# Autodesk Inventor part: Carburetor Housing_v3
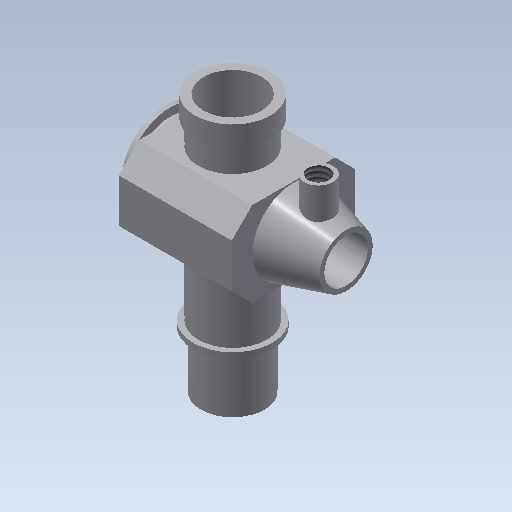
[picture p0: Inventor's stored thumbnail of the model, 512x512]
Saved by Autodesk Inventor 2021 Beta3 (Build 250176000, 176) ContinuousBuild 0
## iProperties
Created: 2012-08
Part Number: Carburetor Housing_v3
Material: Aluminum 6061
Document SubType Name: Modeling
Designer: John
Density: 2.71 g/cm^3
Mass: 9.58727 g
Surface Area: 43.1099 cm^2
Volume: 3.53774 cm^3
Appearance: Aluminum - Flat
Author: John
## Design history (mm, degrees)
sketch "Sketch1"
  geometry: L1 (-9.614, -8.788)-(9.614, -8.788); L2 (9.614, -8.788)-(9.614, 8.788); L3 (9.614, 8.788)-(-9.614, 8.788); L4 (-9.614, 8.788)-(-9.614, -8.788); L5 (-9.614, -8.788)-(9.614, 8.788); 2 further points
  constraints: 10 end point, 2 parallel, 1 coincident, 1 horizontal, 1 midpoint, 1 perpendicular
  dimensions: "d0" = 19.2278 distance of L2.end L3.end; "d2" = 17.5768 distance of L1.end L2.end
extrude "Extrusion1" new body sketch "Sketch1" stored distance "d3" = 13.1572; taper "d4" = 0 deg
sketch "Sketch2"
  geometry: L1 (9.614, 8.788)-(-9.614, 8.788) reference; L2 (-9.614, -8.788)-(9.614, -8.788) reference; L3 (0, 8.788)-(0, -8.788); C1 r 5.321 at (0, 0.686)
  constraints: 2 end point, 2 midpoint, 1 centre point, 1 point on line
  dimensions: "d5" = 10.6426 diameter of C1; "d9" = 8.1026 distance from line of L1 C1.centre
extrude "Extrusion2" join sketch "Sketch2" distance "d7" = 7.0612; taper "d8" = 0 deg
sketch "Sketch8"
  geometry: C1 r 5.321 at (0, 0) reference; C2 r 5.867 at (0, 0); 1 further point
  constraints: 1 centre point, 1 coincident
  dimensions: "d30" = 11.7348 diameter of C2
extrude "Extrusion6" join sketch "Sketch8" distance "d114" = 8.763; taper "d115" = 0 deg
sketch "Sketch3"
  geometry: C1 r 5.321 at (0, 0.686) reference; C2 r 5.321 at (0, 0.686)
  constraints: 1 centre point, 1 coincident
  dimensions: "d10" = 10.6426 diameter of C2
extrude "Extrusion3" join sketch "Sketch3" distance "d32" = 3.2512; taper "d33" = 0 deg
sketch "Sketch4"
  geometry: L1 (0, 0)-(19.228, -13.157); C1 r 5.715 at (9.614, -6.579)
  constraints: 2 end point, 1 centre point, 1 midpoint
  dimensions: "d13" = 11.43 diameter of C1
extrude "Extrusion4" join sketch "Sketch4" distance "d11" = 10.2616; taper "d12" = 0 deg
sketch "Sketch5"
  geometry: C1 r 5.715 at (0, 0) reference; C2 r 6.96 at (0, 0); 1 further point
  constraints: 1 centre point, 1 coincident
  dimensions: "d17" = 13.9192 diameter of C2
extrude "Extrusion5" join sketch "Sketch5" distance "d111" = 0.8382; taper "d112" = 0 deg
sketch "Sketch15"
  geometry: L1 (-16.967, 0)-(-16.967, 4.14); L2 (6.007, -6.579)-(6.007, -16.84) reference; L3 (-4.635, -16.84)-(-4.635, -6.579) reference; L4 (-4.635, -6.579)-(-8.788, -6.579) reference; L5 (-8.788, -6.579)-(-8.788, 6.579) reference; L6 (-8.788, 6.579)-(-4.635, 6.579) reference; L7 (-4.635, 6.579)-(-4.635, 10.389) reference; L8 (-4.635, 10.389)-(-5.182, 10.389) reference; L9 (-5.182, 10.389)-(-5.182, 13.64) reference; L10 (-5.182, 13.64)-(6.553, 13.64) reference; L11 (6.553, 13.64)-(6.553, 10.389) reference; L12 (6.553, 10.389)-(6.007, 10.389) reference; L13 (6.007, 10.389)-(6.007, 6.579) reference; L14 (6.007, 6.579)-(8.788, 6.579) reference; L15 (8.788, 6.579)-(8.788, 5.715) reference; L16 (8.788, 5.715)-(10.389, 5.715) reference; L17 (10.389, 5.715)-(10.389, 6.96) reference; L18 (10.389, 6.96)-(11.074, 6.96) reference; L19 (11.074, 6.96)-(11.074, -6.96) reference; L20 (11.074, -6.96)-(10.389, -6.96) reference; L21 (10.389, -6.96)-(10.389, -5.715) reference; L22 (10.389, -5.715)-(8.788, -5.715) reference; L23 (8.788, -5.715)-(8.788, -6.579) reference; L24 (8.788, -6.579)-(6.007, -6.579) reference; L25 (-8.788, 0)-(-16.967, 0); L26 (-16.967, 4.14)-(-8.788, 6.401); L27 (-8.788, 0)-(-8.788, 6.401); L28 (6.007, -16.84)-(6.845, -16.84) reference; L29 (6.845, -16.84)-(6.845, -17.678) reference; L30 (6.845, -17.678)-(5.639, -17.678) reference; L31 (5.639, -17.678)-(5.639, -26.441) reference; L32 (5.639, -26.441)-(-4.267, -26.441) reference; L33 (-4.267, -26.441)-(-4.267, -17.678) reference; L34 (-4.267, -17.678)-(-5.474, -17.678) reference; L35 (-5.474, -17.678)-(-5.474, -16.84) reference; L36 (-5.474, -16.84)-(-4.635, -16.84) reference; 1 further point
  constraints: 8 end point, 1 collinear, 1 midpoint, 1 parallel, 1 point on line
  dimensions: "d119" = 4.1402 distance of L1.start L1.end; "d136" = 8.1788 distance of L25.start L1.start; "d137" = 6.4008 distance from line of L25 L26.end
revolve "Revolution1" sketch "Sketch15" stored, may be unused: angle "d120" = 90 deg
hole "Hole2" diameter "d68" = 9.0678; stored, may be unused: countersink angle "d72" = 82 deg, drill point angle "d74" = 0 deg; dims "d69" = 19.05, "d70" = 9.525, "d71" = 6.35, "d73" = 16.8402, "d105" = 25.4, "d106" = 25.4
hole "Hole4" diameter "d153" = 3.302; stored, may be unused: countersink angle "d157" = 82 deg, drill point angle "d159" = 118 deg; dims "d151" = 25.4, "d152" = 25.4, "d154" = 19.05, "d155" = 9.525, "d156" = 6.35, "d158" = 25.4
chamfer "Chamfer1" distance "d101" = 3.175; stored, may be unused: second distance "d102" = 3.175, angle "d103" = 45 deg
body "Solid1"
extrude "Extrusion7" join sketch "Sketch4" distance "d15" = 2.286; taper "d16" = 0 deg
extrude "Extrusion8" join sketch "Sketch5" distance "d19" = 0.6858; taper "d20" = 0 deg
sketch "Sketch17"
  geometry: L1 (-9.614, -8.788)-(-9.614, 8.788) reference; L2 (-9.614, 8.788)-(-5.715, 8.788) reference; L3 (-5.715, 8.788)-(-5.715, 10.389) reference; L4 (-5.715, 10.389)-(-6.96, 10.389) reference; L5 (-6.96, 10.389)-(-6.96, 11.074) reference; L6 (-6.96, 11.074)-(6.96, 11.074) reference; L7 (6.96, 11.074)-(6.96, 10.389) reference; L8 (6.96, 10.389)-(5.715, 10.389) reference; L9 (5.715, 10.389)-(5.715, 8.788) reference; L10 (5.715, 8.788)-(9.614, 8.788) reference; L11 (9.614, 8.788)-(9.614, -8.788) reference; L12 (9.614, -8.788)-(6.401, -8.788) reference; L13 (6.401, -8.788)-(4.14, -16.967) reference; L14 (4.14, -16.967)-(-4.14, -16.967) reference; L15 (-4.14, -16.967)-(-6.401, -8.788) reference; L16 (-6.401, -8.788)-(-9.614, -8.788) reference; L17 (0, -16.967)-(0, -12.7); C1 r 2.223 at (0, -12.7); 1 further point
  constraints: 2 end point, 1 centre point, 1 coincident, 1 midpoint, 1 perpendicular
  dimensions: "d138" = 4.2672 distance of L17.start L17.end; "d139" = 4.445 diameter of C1
extrude "Extrusion9" join sketch "Sketch17" distance "d140" = 9.525; taper "d141" = 0 deg
hole "Hole1" diameter "d45" = 10.5918; stored, may be unused: countersink angle "d49" = 82 deg, drill point angle "d51" = 0 deg; dims "d43" = 25.4, "d44" = 25.4, "d46" = 19.05, "d47" = 9.525, "d48" = 6.35, "d50" = 16.8402
hole "Hole3" diameter "d144" = 6.8072; stored, may be unused: countersink angle "d148" = 82 deg, drill point angle "d150" = 118 deg; dims "d145" = 19.05, "d146" = 9.525, "d147" = 6.35, "d149" = 25.4, "d160" = 25.4, "d161" = 25.4
sketch "Sketch12"
  geometry: C1 r 5.321 at (0, 0) reference; C2 r 6.159 at (0, 0); 1 further point
  constraints: 1 centre point, 1 coincident
  dimensions: "d109" = 12.319 diameter of C2
sketch "Sketch13"
  geometry: C1 r 6.159 at (0, 0) reference; C2 r 4.953 at (0, 0)
  constraints: 1 centre point, 1 coincident
  dimensions: "d113" = 9.906 diameter of C2
node "Project Cut Edges3"
node "Project Cut Edges4"
